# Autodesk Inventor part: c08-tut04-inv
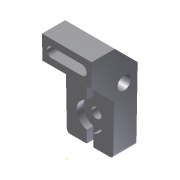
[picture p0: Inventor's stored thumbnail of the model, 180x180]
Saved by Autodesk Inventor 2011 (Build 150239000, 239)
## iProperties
Created: 2010-03
Part Number: c08-tut04-inv
Document SubType Name: Modeling
Designer: CADSoft
Density: 1 g/cm^3
Author: CADSoft
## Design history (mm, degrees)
sketch "Sketch1"
  geometry: 1 further point
sketch "Sketch2"
  geometry: L1 (0, 58)-(14, 58); L2 (28, 44)-(28, 0); L3 (28, 0)-(14, 0); L4 (0, 44)-(0, 58); L5 (0, 44)-(14, 30); L6 (14, 30)-(14, 0); L7 (14, 58)-(28, 44); C1 r 4 at (20, 37); 1 further point
  constraints: 14 end point, 3 parallel, 1 centre point, 1 horizontal, 1 perpendicular, 1 point on line, 1 vertical
  dimensions: "d2" = 14 distance of L4.start L1.start; "d3" = 28 distance between parallel lines of L2 L4; "d4" = 14 distance from line of L2 L1.end; "d5" = 14 distance from line of L2.start L1; "d6" = 58 distance between parallel lines of L3 L1; "d7" = 14 distance of L2.end L3.end; "d8" = 8 diameter of C1; "d9" = 21 distance from line of L1 C1.centre; "d10" = 8 distance from line of L2 C1.centre
extrude "Extrusion1" new body sketch "Sketch2" stored distance "d11" = 30; taper "d12" = 0 deg
sketch "Sketch3"
  geometry: L1 (30, 0)-(0, 0) reference; L2 (30, -30)-(0, -30) reference; L3 (13, 0)-(17, 0); L4 (17, -30)-(13, -30); L5 (13, -7.254)-(13, 0); L6 (17, 0)-(17, -7.254); L7 (13, -30)-(13, -22.746); L8 (17, -22.746)-(17, -30); A1 r 8 centre (15, -15) between (13, -7.254) and (13, -22.746); A2 r 8 centre (15, -15) between (17, -22.746) and (17, -7.254); 2 further points
  constraints: 12 end point, 5 parallel, 4 point on circle, 2 centre point, 2 perpendicular, 2 point on line, 1 horizontal, 1 midpoint
  dimensions: "d13" = 4 distance of L4.start L4.end; "d17" = 8 radius of A1; "d18" = 2 distance from line of L8 A1.centre; "d19" = 15 distance from line of L2 A1.centre
extrude "Extrusion2" cut sketch "Sketch3" distance "d20" = 4; taper "d21" = 0 deg
hole "Hole1" diameter "d24" = 6; stored, may be unused: countersink angle "d28" = 90 deg, drill point angle "d30" = 118 deg; dims "d22" = 10, "d23" = 10, "d25" = 6, "d26" = 4, "d27" = 2, "d29" = 8
sketch "Sketch4"
  geometry: L1 (0, 0)-(30, 0) reference; L2 (30, -14)-(0, -14) reference; L3 (5.49, -4.022)-(24, -4.022); L4 (24, -9.978)-(6, -9.978); A1 r 2.978 centre (24, -7) between (24, -9.978) and (24, -4.022); A2 r 3 centre (6, -6.978) between (5.49, -4.022) and (6, -9.978); 1 further point
  constraints: 4 end point, 4 point on circle, 3 tangent, 2 centre point, 2 parallel
  dimensions: "d31" = 18 distance of A1.centre A2.centre; "d32" = 9 horizontal distance of point (15, -58) A1.centre; "d33" = 7 distance from line of L1 A1.centre; "d34" = 3 radius of A2
extrude "Extrusion3" cut sketch "Sketch4" distance "d35" = 11; taper "d36" = 0 deg
feature "FaceDraft1" dims angle "d37" = 1 deg
fillet "Fillet1" dims "d38" = 2
body "Solid1"
other parameters: "d14" = 2, "d15" = 16
